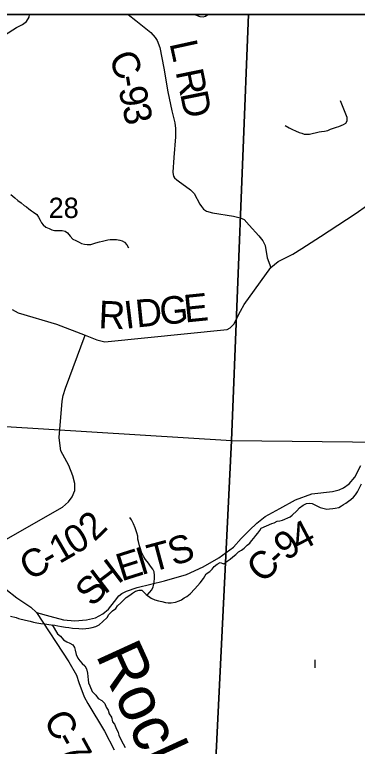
# Model space of a CAD drawing. Extents: x 0 to 34, y 0 to 22.
# Drawn here: x 6.965 to 7.672, y 19.391 to 20.9 of the extents above; entities that cross this region are included whole.
import ezdxf

# ---------------------------------------------------------------- set-up
doc = ezdxf.new("R2010")
doc.units = 0
for name, color, linetype in [('Default', 7, 'Continuous'), ('GM_X_County_Road', 7, 'Continuous'), ('GM_X_County_Road_Text', 7, 'Continuous'), ('GM_X_Minor_River', 7, 'Continuous'), ('GM_X_Minor_River_Text', 7, 'Continuous'), ('GM_X_Section', 7, 'Continuous'), ('GM_X_Section_Text', 7, 'Continuous'), ('GM_X_State_Route', 7, 'Continuous'), ('SH_Data', 7, 'Continuous')]:
    doc.layers.add(name, color=color, linetype=linetype)

msp = doc.modelspace()

# ---------------------------------------------------------------- linework, layer by layer
at = {"layer": 'Default'}
for points in [[(7.4473, 20.9), (6.898, 20.9), (6.8905, 20.8862), (6.8831, 20.8788), (6.8772, 20.8714), (6.8677, 20.8519), (6.8545, 20.8401), (6.8379, 20.8269), (6.8281, 20.8138), (6.8084, 20.7969), (6.7976, 20.7888), (6.7851, 20.7759), (6.7734, 20.7614), (6.7572, 20.7474), (6.7425, 20.7348), (6.7286, 20.7246), (6.7247, 20.7201), (6.7215, 20.7141), (6.6475, 20.0689), (7.4124, 20.0219)], [(8.7465, 20.9), (7.4473, 20.9), (7.4124, 20.0219), (8.6611, 20.0077)]]:
    msp.add_lwpolyline(points, close=True, dxfattribs=at)
at = {"layer": 'GM_X_County_Road'}
for points in [[(6.9443, 20.8579), (6.969, 20.8732), (6.9813, 20.8797), (6.9895, 20.8859), (6.9954, 20.8945), (6.9962, 20.9)], [(7.1991, 20.9), (7.2149, 20.8878), (7.2463, 20.8629), (7.255, 20.8528), (7.2591, 20.8466), (7.2644, 20.8321), (7.2729, 20.7897), (7.2809, 20.7408), (7.2894, 20.7013), (7.2957, 20.6768), (7.2969, 20.6649), (7.2968, 20.6479), (7.2933, 20.6051), (7.2915, 20.5749), (7.2919, 20.5702), (7.293, 20.5668), (7.295, 20.5635), (7.2995, 20.5591), (7.305, 20.5555), (7.3177, 20.5462), (7.3278, 20.5387), (7.3355, 20.5311), (7.3473, 20.5088), (7.3505, 20.5043), (7.3549, 20.4989), (7.361, 20.4945), (7.3734, 20.4909), (7.4165, 20.4842), (7.4305, 20.4807), (7.4385, 20.4773), (7.4492, 20.4661), (7.469, 20.4441), (7.4772, 20.4335), (7.4817, 20.4237), (7.4864, 20.3987), (7.4936, 20.3787)], [(6.9603, 20.292), (6.9727, 20.2847), (7.0513, 20.2617), (7.1104, 20.2391), (7.1346, 20.229), (7.1513, 20.2253), (7.4033, 20.2509), (7.4098, 20.2538), (7.4173, 20.2615), (7.4309, 20.2881), (7.4389, 20.302), (7.4936, 20.3787), (7.5091, 20.3906), (7.5387, 20.4058), (7.5579, 20.4174), (7.5963, 20.4427), (7.6673, 20.4891), (7.6929, 20.5069)], [(6.9026, 19.7617), (6.9073, 19.7799), (6.9157, 19.7961), (6.9261, 19.8081), (6.9469, 19.8173), (7.0642, 19.8839), (7.076, 19.8949), (7.0842, 19.9057), (7.0892, 19.9185), (7.0896, 19.9329), (7.0855, 19.949), (7.0773, 19.9698), (7.0607, 20.0003), (7.0591, 20.0106), (7.057, 20.0277), (7.0632, 20.103), (7.0653, 20.1145), (7.0701, 20.1296), (7.1104, 20.2391)], [(7.0106, 19.6671), (7.038, 19.6597), (7.0662, 19.6521), (7.0892, 19.6498), (7.1137, 19.6515), (7.1319, 19.6562), (7.1471, 19.6642), (7.1588, 19.674), (7.1712, 19.6899), (7.18, 19.7011), (7.1866, 19.7064), (7.1962, 19.7111), (7.2176, 19.7183), (7.2746, 19.7325), (7.3195, 19.7454), (7.354, 19.761), (7.3866, 19.7796), (7.4164, 19.8018), (7.4325, 19.8194), (7.4495, 19.8368), (7.4648, 19.8509), (7.4821, 19.8651), (7.5121, 19.8814), (7.5444, 19.8992), (7.5784, 19.9119), (7.6205, 19.9168), (7.6347, 19.9202), (7.6435, 19.9241), (7.6553, 19.9321), (7.6667, 19.9459), (7.6796, 19.9704)], [(6.9469, 19.7152), (6.9695, 19.6969), (6.9984, 19.6779), (7.0106, 19.6671)], [(7.0106, 19.6671), (7.0769, 19.5653), (7.0925, 19.5374), (7.0976, 19.5224), (7.1088, 19.4927), (7.116, 19.4794), (7.1506, 19.4223), (7.1704, 19.384)]]:
    msp.add_lwpolyline(points, dxfattribs=at)
at = {"layer": 'GM_X_Minor_River'}
for points in [[(7.3378, 20.9), (7.3383, 20.8996), (7.3473, 20.8961), (7.3542, 20.8956), (7.3588, 20.897), (7.3638, 20.9), (7.3638, 20.9)], [(7.5229, 20.6715), (7.5316, 20.6664), (7.538, 20.6633), (7.5448, 20.6601), (7.5523, 20.6569), (7.5573, 20.6553), (7.5626, 20.6533), (7.569, 20.6532), (7.5736, 20.6535), (7.579, 20.655), (7.5881, 20.6571), (7.5935, 20.6582), (7.5981, 20.6589), (7.6045, 20.6599), (7.6114, 20.6609), (7.6168, 20.6635), (7.6229, 20.6657), (7.6291, 20.6679), (7.634, 20.6693), (7.6386, 20.6711), (7.6436, 20.6734), (7.6486, 20.6763), (7.6514, 20.6808), (7.6511, 20.6877), (7.6373, 20.7222)], [(6.9577, 20.5287), (6.9656, 20.5225), (6.9715, 20.5167), (6.9787, 20.512), (6.9847, 20.5065), (6.9899, 20.5034), (6.9944, 20.4995), (6.9997, 20.4956), (7.0042, 20.4925), (7.011, 20.4875), (7.0147, 20.4824), (7.018, 20.4759), (7.0206, 20.4709), (7.0243, 20.4663), (7.0295, 20.4616), (7.0363, 20.4592), (7.042, 20.4565), (7.0473, 20.4549), (7.0576, 20.4547), (7.0633, 20.455), (7.0694, 20.4534), (7.0739, 20.4499), (7.0795, 20.4433), (7.0854, 20.4371), (7.0911, 20.4343), (7.0983, 20.4304), (7.1032, 20.4281), (7.1096, 20.4264), (7.1145, 20.426), (7.1222, 20.4262), (7.1329, 20.4291), (7.1405, 20.4313), (7.1463, 20.4331), (7.152, 20.4345), (7.1574, 20.4356), (7.1623, 20.4362), (7.1684, 20.4365), (7.1756, 20.4364), (7.1821, 20.4348), (7.187, 20.4335), (7.1919, 20.4308), (7.1968, 20.4254), (7.2001, 20.4192)], [(7.4958, 19.8502), (7.5004, 19.8521), (7.5065, 19.855), (7.5119, 19.8561), (7.518, 19.8571), (7.5333, 19.8645), (7.5379, 19.8675), (7.5476, 19.8768), (7.5531, 19.8825), (7.5604, 19.8881), (7.5669, 19.8921), (7.5734, 19.8924), (7.5787, 19.8916), (7.5855, 19.8884), (7.5901, 19.886), (7.5957, 19.8833), (7.609, 19.8804), (7.6147, 19.8807), (7.6216, 19.8813), (7.6265, 19.882), (7.6342, 19.8838), (7.6392, 19.8872), (7.6438, 19.8894), (7.6484, 19.8923), (7.6538, 19.8968), (7.6588, 19.9002), (7.6643, 19.9047), (7.6681, 19.9095), (7.6721, 19.9156), (7.6807, 19.9322)], [(7.2389, 19.7026), (7.2482, 19.714), (7.2507, 19.72), (7.252, 19.7253), (7.2535, 19.7363), (7.2537, 19.7431), (7.2529, 19.7507), (7.25, 19.7561), (7.2453, 19.7628), (7.2413, 19.7686), (7.2351, 19.776), (7.2319, 19.7818), (7.2269, 19.7911), (7.2245, 19.7981), (7.2225, 19.8046), (7.2209, 19.8134), (7.2191, 19.8184), (7.219, 19.8241), (7.2173, 19.831), (7.2139, 19.8418), (7.2107, 19.8495), (7.2065, 19.858), (7.2025, 19.8631)], [(7.389, 19.7704), (7.3966, 19.767), (7.4036, 19.7725), (7.4098, 19.7772), (7.4153, 19.7816), (7.4215, 19.7863), (7.427, 19.7918), (7.4332, 19.7958), (7.4383, 19.7994), (7.445, 19.8056), (7.4501, 19.81), (7.454, 19.8148), (7.4584, 19.8204), (7.4624, 19.8255), (7.4667, 19.8303), (7.4707, 19.8359), (7.4735, 19.8407), (7.4958, 19.8502)], [(6.9566, 19.6595), (6.9683, 19.6564), (6.9735, 19.6547), (6.9878, 19.6512), (6.9969, 19.6494), (7.0044, 19.6468), (7.0112, 19.6458), (7.0195, 19.6444), (7.0274, 19.6434), (7.0357, 19.642), (7.0407, 19.6418), (7.0482, 19.6408), (7.0543, 19.6394), (7.0622, 19.6384), (7.0701, 19.637), (7.0769, 19.636), (7.0845, 19.6349), (7.0973, 19.6341), (7.1042, 19.6335), (7.1118, 19.634), (7.1183, 19.6349), (7.1251, 19.6358), (7.1328, 19.6378), (7.1394, 19.6418), (7.1472, 19.6483), (7.1562, 19.6568), (7.1598, 19.6627), (7.1669, 19.6705), (7.1739, 19.6752), (7.1775, 19.6804), (7.1842, 19.687), (7.1952, 19.6976), (7.203, 19.703), (7.2084, 19.7067), (7.2147, 19.711), (7.2223, 19.713), (7.2273, 19.7132), (7.2368, 19.7041), (7.2468, 19.6966), (7.2547, 19.6933), (7.2622, 19.6907), (7.2686, 19.6894), (7.2761, 19.6876), (7.2822, 19.687), (7.2882, 19.6868), (7.297, 19.6884), (7.3047, 19.6912), (7.3097, 19.6929), (7.3148, 19.6973), (7.3202, 19.6997), (7.3272, 19.7056), (7.3367, 19.7155), (7.3481, 19.728), (7.3549, 19.7369), (7.3606, 19.747), (7.3679, 19.7513), (7.3726, 19.7561), (7.377, 19.7616), (7.3829, 19.7664), (7.389, 19.7704)], [(7.0429, 19.6415), (7.0537, 19.6231), (7.0596, 19.6179), (7.0662, 19.6109), (7.0729, 19.6065), (7.0788, 19.6036), (7.0852, 19.6), (7.0888, 19.5945), (7.0901, 19.5891), (7.0921, 19.5803), (7.0956, 19.573), (7.1, 19.5671), (7.1047, 19.5617), (7.1102, 19.5569), (7.1131, 19.5511), (7.1158, 19.5415), (7.1172, 19.5282), (7.1178, 19.5217), (7.1202, 19.5159), (7.1248, 19.5043), (7.1328, 19.4968), (7.1375, 19.4898), (7.1454, 19.4858), (7.1512, 19.4791), (7.154, 19.4714), (7.158, 19.4656), (7.16, 19.4583), (7.1647, 19.4513), (7.1674, 19.4417), (7.1714, 19.4366), (7.1738, 19.4297), (7.1788, 19.4196), (7.1801, 19.4142), (7.1833, 19.4065), (7.1893, 19.3961), (7.1933, 19.3883)], [(7.5854, 19.5526), (7.5849, 19.5693)]]:
    msp.add_lwpolyline(points, dxfattribs=at)
at = {"layer": 'GM_X_Section'}
for points in [[(6.6475, 20.0689), (7.4124, 20.0219), (7.3629, 19.0139), (6.5612, 19.0743)], [(7.4124, 20.0219), (8.6611, 20.0077), (8.567, 18.9616), (7.3629, 19.0139)]]:
    msp.add_lwpolyline(points, close=True, dxfattribs=at)
at = {"layer": 'GM_X_State_Route'}
msp.add_lwpolyline([(8.9, 16.8616), (8.9, 20.9), (6.8697, 20.9), (6.7177, 20.7411), (6.6525, 20.7169), (6.5075, 20.7281), (6.4321, 20.7553), (6.3691, 20.7729), (6.282, 20.7835), (6.2399, 20.787), (6.2051, 20.7905), (6.1295, 20.8038), (6.0609, 20.8242), (5.9975, 20.8551), (5.9272, 20.8941), (5.9107, 20.9), (5.6847, 20.9)], dxfattribs=at)
at = {"layer": 'SH_Data'}
msp.add_line((2.1, 20.9), (8.9, 20.9), dxfattribs=at)

# ---------------------------------------------------------------- texts
at = {"layer": 'GM_X_County_Road_Text'}
for s, rotation, p in [('L', 282.3438, (7.2844, 20.841)), ('C', 294.7495, (7.1575, 20.8102)), ('R', 281.5545, (7.2969, 20.7825)), ('-', 279.1858, (7.1758, 20.7717)), ('9', 279.9008, (7.1797, 20.7479)), ('D', 281.4166, (7.3063, 20.7369)), ('3', 283.4768, (7.1865, 20.7096)), ('D', 5.7982, (7.2172, 20.2547)), ('G', 5.8009, (7.2669, 20.2597)), ('E', 5.7997, (7.3166, 20.2648)), ('R', 357.4662, (7.1374, 20.2535)), ('I', 6.9299, (7.1943, 20.2519)), ('2', 44.4472, (7.1299, 19.8115)), ('0', 31.2612, (7.0887, 19.7846)), ('4', 27.7002, (7.5526, 19.7913)), ('9', 35.7783, (7.526, 19.772)), ('1', 30.1102, (7.0574, 19.7664)), ('T', 14.9902, (7.2479, 19.7501)), ('S', 18.7479, (7.2928, 19.7622)), ('C', 29.7521, (6.9963, 19.7315)), ('I', 16.6734, (7.2259, 19.7435)), ('-', 29.8389, (7.0369, 19.7547)), ('E', 17.5079, (7.1856, 19.7308)), ('C', 43.4992, (7.4766, 19.7252)), ('-', 42.9256, (7.5103, 19.7573)), ('H', 37.2522, (7.1504, 19.7029)), ('S', 46.7499, (7.126, 19.6766)), ('C', 298.82, (7.0234, 19.4463)), ('7', 298.9821, (7.057, 19.3853)), ('-', 298.9652, (7.0458, 19.4055))]:
    msp.add_text(s, height=0.0568, rotation=rotation, dxfattribs=at).set_placement(p)
at = {"layer": 'GM_X_Minor_River_Text'}
msp.add_text('Rock', height=0.0947, rotation=294.5569, dxfattribs=at).set_placement((7.1316, 19.5798))
at = {"layer": 'GM_X_Section_Text'}
msp.add_text('28', height=0.04186, rotation=0, dxfattribs=at).set_placement((7.0352, 20.4806))

doc.saveas('drawing.dxf')
